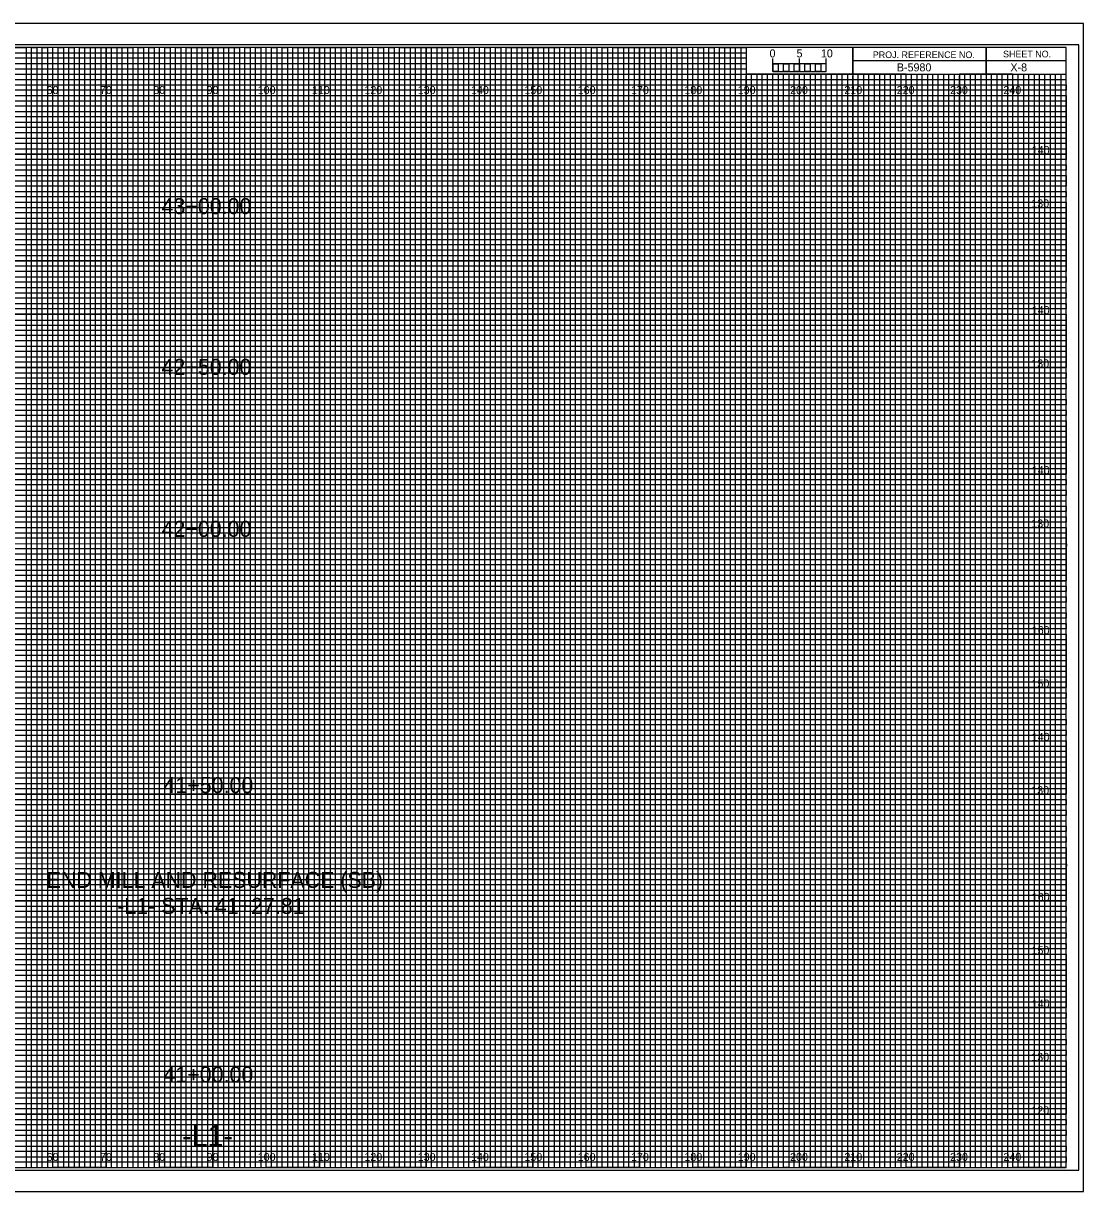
# Model space of a CAD drawing. Extents: x -13 to 323, y -5 to 3294.
# Drawn here: x 124.5 to 323.3, y 1535.5 to 1754.5 of the extents above; entities that cross this region are included whole.
import ezdxf

# ---------------------------------------------------------------- set-up
doc = ezdxf.new("R2010")
doc.units = 0
for name, color, linetype in [('Prop XS Alignment Label', 7, 'Continuous'), ('Prop XS Bar Scale Labels', 7, 'Continuous'), ('Prop XS Elevation Labels', 7, 'Continuous'), ('Prop XS Offset Labels', 7, 'Continuous'), ('Prop XS Project Number', 7, 'Continuous'), ('Prop XS Sheet Number', 7, 'Continuous'), ('Prop XS Station Labels', 7, 'Continuous'), ('Scratch_Level_0', 7, 'Continuous'), ('Sheet Cross Section CELL', 7, 'Continuous'), ('Sheet Cross Section Grid Major CELL', 7, 'Continuous'), ('Sheet Cross Section Grid Middle CELL', 7, 'Continuous'), ('Sheet Cross Section Grid Minor 1 CELL', 7, 'Continuous'), ('Sheet Cross Section Grid Minor 2 CELL', 7, 'Continuous'), ('Sheet Cross Section Scale CELL', 7, 'Continuous'), ('Sheet Cutting Line CELL', 7, 'Continuous'), ('Sheet DOT Grid CELL', 7, 'Continuous'), ('Sheet Plot Border Inside CELL', 7, 'Continuous'), ('Sheet Plot Border Outside CELL', 7, 'Continuous')]:
    doc.layers.add(name, color=color, linetype=linetype)

msp = doc.modelspace()

# ---------------------------------------------------------------- linework, layer by layer
at = {"layer": 'Scratch_Level_0'}
for points in [[(310, 1730), (10, 1730), (10, 1710), (310, 1710)], [(310, 1700), (10, 1700), (10, 1680), (310, 1680)], [(310, 1670), (10, 1670), (10, 1650), (310, 1650)], [(315, 1640), (10, 1640), (10, 1605), (315, 1605)], [(310, 1590), (10, 1590), (10, 1555), (310, 1555)]]:
    msp.add_lwpolyline(points, close=True, dxfattribs=at)
at = {"layer": 'Sheet Cross Section CELL'}
for p, q in [((305, 1750), (305, 1745)), ((305, 1745), (305, 1750)), ((280, 1747.5), (280, 1745)), ((320, 1747.49), (280, 1747.49)), ((280, 1745), (320, 1745))]:
    msp.add_line(p, q, dxfattribs=at)
for points in [[(320, 1750), (0, 1750), (0, 1540), (320, 1540)], [(280, 1750), (260, 1750), (260, 1745.03), (280, 1745.03)], [(320, 1750), (280, 1750), (280, 1745), (320, 1745)]]:
    msp.add_lwpolyline(points, close=True, dxfattribs=at)
at = {"layer": 'Sheet Cross Section Grid Major CELL'}
for p, q in [((130, 1750), (120, 1750)), ((130, 1540), (130, 1750)), ((150, 1750), (140, 1750)), ((140, 1750), (140, 1540)), ((150, 1540), (150, 1750)), ((170, 1750), (160, 1750)), ((160, 1750), (160, 1540)), ((170, 1540), (170, 1750)), ((190, 1750), (180, 1750)), ((180, 1750), (180, 1540)), ((190, 1540), (190, 1750)), ((210, 1750), (200, 1750)), ((200, 1750), (200, 1540)), ((210, 1540), (210, 1750)), ((230, 1750), (220, 1750)), ((220, 1750), (220, 1540)), ((230, 1540), (230, 1750)), ((250, 1750), (240, 1750)), ((240, 1750), (240, 1540)), ((250, 1540), (250, 1750)), ((260, 1750), (260, 1540)), ((270, 1540), (270, 1745)), ((290, 1745), (280, 1745)), ((280, 1745), (280, 1540)), ((290, 1540), (290, 1745)), ((310, 1745), (300, 1745)), ((300, 1745), (300, 1540)), ((310, 1540), (310, 1745)), ((140, 1540), (130, 1540)), ((160, 1540), (150, 1540)), ((180, 1540), (170, 1540)), ((200, 1540), (190, 1540)), ((220, 1540), (210, 1540)), ((240, 1540), (230, 1540)), ((260, 1540), (250, 1540)), ((280, 1540), (270, 1540)), ((300, 1540), (290, 1540)), ((320, 1540), (310, 1540)), ((320, 1540), (320, 1540))]:
    msp.add_line(p, q, dxfattribs=at)
for points in [[(0, 1740), (320, 1740), (320, 1730), (0, 1730)], [(0, 1720), (320, 1720), (320, 1710), (0, 1710)], [(0, 1700), (320, 1700), (320, 1690), (0, 1690)], [(0, 1680), (320, 1680), (320, 1670), (0, 1670)], [(0, 1660), (320, 1660), (320, 1650), (0, 1650)], [(0, 1640), (320, 1640), (320, 1630), (0, 1630)], [(0, 1620), (320, 1620), (320, 1610), (0, 1610)], [(0, 1600), (320, 1600), (320, 1590), (0, 1590)], [(0, 1580), (320, 1580), (320, 1570), (0, 1570)], [(0, 1560), (320, 1560), (320, 1550), (0, 1550)]]:
    msp.add_lwpolyline(points, dxfattribs=at)
at = {"layer": 'Sheet Cross Section Grid Middle CELL'}
for points in [[(115, 1750), (125, 1750), (125, 1540), (135, 1540), (135, 1750), (145, 1750), (145, 1540), (155, 1540), (155, 1750), (165, 1750), (165, 1540), (175, 1540), (175, 1750), (185, 1750), (185, 1540), (195, 1540), (195, 1750), (205, 1750), (205, 1540), (215, 1540), (215, 1750), (225, 1750), (225, 1540), (235, 1540), (235, 1750), (245, 1750), (245, 1540), (255, 1540), (255, 1750), (259.93, 1750), (260, 1750), (260, 1745), (264.99, 1745), (264.99, 1540), (275, 1540), (275, 1745), (285, 1745), (285, 1540), (295, 1540), (295, 1745), (305, 1745), (305, 1540), (315, 1540), (315, 1745)], [(0, 1745), (275, 1745)], [(0, 1725), (320, 1725), (320, 1735), (0, 1735)], [(0, 1705), (320, 1705), (320, 1715), (0, 1715)], [(0, 1685), (320, 1685), (320, 1695), (0, 1695)], [(0, 1665), (320, 1665), (320, 1675), (0, 1675)], [(0, 1645), (320, 1645), (320, 1655), (0, 1655)], [(0, 1625), (320, 1625), (320, 1635), (0, 1635)], [(0, 1605), (320, 1605), (320, 1615), (0, 1615)], [(0, 1585), (320, 1585), (320, 1595), (0, 1595)], [(0, 1565), (320, 1565), (320, 1575), (0, 1575)], [(0, 1545), (320, 1545), (320, 1555), (0, 1555)]]:
    msp.add_lwpolyline(points, dxfattribs=at)
at = {"layer": 'Sheet Cross Section Grid Minor 1 CELL'}
for p, q in [((0, 1749), (260, 1749)), ((260, 1747.98), (0, 1747.98)), ((260, 1749), (260, 1747.98)), ((0, 1747), (260, 1747)), ((260, 1745.89), (0, 1745.89)), ((260, 1747), (260, 1745.89)), ((0, 1744), (320, 1744))]:
    msp.add_line(p, q, dxfattribs=at)
for points in [[(0, 1743), (270, 1743), (320, 1743), (320, 1742), (0, 1742)], [(0, 1741), (320, 1741), (320, 1739), (0, 1739)], [(0, 1738), (320, 1738), (320, 1737), (0, 1736.98)], [(0, 1736), (320, 1736), (320, 1734), (0, 1734)], [(0, 1733), (320, 1733), (320, 1732), (0, 1732)], [(0, 1731), (320, 1731), (320, 1729), (0, 1729)], [(0, 1728), (320, 1728), (320, 1727), (0, 1727)], [(0, 1726), (320, 1726), (320, 1724), (0, 1724)], [(0, 1723), (320, 1723), (320, 1722), (0, 1722)], [(0, 1721), (320, 1721), (320, 1719), (0, 1719)], [(0, 1718), (320, 1718), (320, 1717), (0, 1717)], [(0, 1716), (320, 1716), (320, 1713.95), (320, 1713), (320, 1712), (0, 1712)], [(0, 1714), (320, 1714), (320, 1713), (0, 1713)], [(0, 1711), (320, 1711), (320, 1709), (0, 1709.03)], [(0, 1709.03), (320, 1709), (320, 1708), (0, 1708)], [(0, 1707), (320, 1707), (320, 1706), (0, 1706)], [(0, 1704), (320, 1704), (320, 1703), (0, 1703)], [(0, 1702), (320, 1702), (320, 1701), (0, 1701)], [(-0.07, 1698.89), (320, 1698.89), (320, 1697.88), (-0.07, 1697.88)], [(0, 1697), (320, 1697), (320, 1696), (0, 1696)], [(0, 1694), (320, 1694), (320, 1693), (0, 1693)], [(0, 1692), (320, 1692), (320, 1691), (0, 1691)], [(0, 1689), (320, 1689), (320, 1688), (0, 1688)], [(0, 1687), (320, 1687), (320, 1686), (0, 1686)], [(0, 1684), (320, 1684), (320, 1683), (0, 1683)], [(0, 1682), (320, 1682), (320, 1681), (0, 1681)], [(0, 1679), (320, 1679), (319.99, 1677.98), (0, 1678)], [(0, 1677), (320, 1677), (320, 1676), (0, 1676)], [(0, 1674), (320, 1674), (320, 1673), (0, 1673)], [(0, 1672), (320, 1672), (320, 1671), (0, 1671)], [(0, 1669), (320, 1669), (320, 1668), (0, 1668)], [(0, 1667), (320, 1667), (320, 1666), (0, 1666)], [(0, 1664), (320, 1664), (320, 1663), (0, 1663)], [(0, 1662), (320, 1662), (320, 1661), (0, 1661)], [(0, 1659), (320, 1659), (320, 1658), (0, 1658)], [(0, 1656.99), (320.07, 1656.91), (320, 1656), (0, 1656)], [(0, 1654), (320, 1654), (320, 1653), (0, 1653)], [(0, 1652), (320, 1652), (320, 1651), (0, 1651)], [(0, 1649), (320, 1649), (320, 1648), (0, 1648)], [(0, 1647), (320, 1647), (320, 1646), (0, 1646)], [(0, 1644), (320, 1644), (320, 1643), (0, 1643)], [(0, 1642), (320, 1642), (320, 1641), (0, 1641)], [(0, 1639), (320, 1639), (320, 1638), (0, 1638)], [(0, 1637), (320, 1637), (320, 1636), (0, 1636)], [(0, 1634), (320, 1634), (320, 1633), (0, 1633)], [(0, 1632), (320, 1632), (320, 1631), (0, 1631)], [(0, 1629), (320, 1629), (320, 1628), (0, 1628)], [(0, 1627), (320, 1627), (320, 1626), (0, 1626)], [(0, 1624), (320, 1624), (320, 1623), (0, 1623)], [(0, 1622), (320, 1622), (320, 1621), (0, 1621)], [(0, 1619), (320, 1619), (319.99, 1617.98), (0, 1618)], [(0, 1617), (320, 1617), (320, 1616), (0, 1616)], [(0, 1614), (320, 1614), (320, 1613), (0, 1613)], [(0, 1612), (320, 1612), (320, 1611), (0, 1611)], [(0, 1609), (320, 1609), (320, 1608), (0, 1608)], [(0, 1607), (320, 1607), (320, 1606), (0, 1606)], [(0, 1604), (320, 1604), (320, 1603), (0, 1603)], [(0, 1602), (320, 1602), (320, 1601), (0, 1601)], [(0, 1599), (320, 1599), (320, 1598), (0, 1598)], [(0, 1596.99), (320.07, 1596.91), (320, 1596), (0, 1596)], [(0, 1594), (320, 1594), (320, 1593), (0, 1593)], [(0, 1592), (320, 1592), (320, 1591), (0, 1591)], [(0, 1589), (320, 1589), (320, 1588), (0, 1588)], [(0, 1587), (320, 1587), (320, 1586), (0, 1586)], [(0, 1584), (320, 1584), (320, 1583), (0, 1583)], [(0, 1582), (320, 1582), (320, 1581), (0, 1581)], [(0, 1579), (320, 1579), (320, 1578), (0, 1578)], [(0, 1577), (320, 1577), (320, 1576), (0, 1576)], [(0, 1574), (320, 1574), (320, 1573), (0, 1573)], [(0, 1572), (320, 1572), (320, 1571), (0, 1571)], [(0, 1569), (320, 1569), (320, 1568), (0, 1568)], [(0, 1567), (320, 1567), (320, 1566), (0, 1566)], [(0, 1564), (320, 1564), (320, 1563), (0, 1563)], [(0, 1562), (320, 1562), (320, 1561), (0, 1561)], [(0, 1559), (320, 1559), (320, 1558), (0, 1558)], [(0, 1557), (320, 1557), (320, 1556), (0, 1556)], [(0, 1554), (320, 1554), (320, 1553), (0, 1553)], [(0, 1552), (320, 1552), (320, 1551), (0, 1551)], [(0, 1549), (320, 1549), (320, 1548), (0, 1548)], [(0, 1547), (320, 1547), (320, 1546), (0, 1546)], [(0, 1544), (320, 1544), (320, 1543), (0, 1543)], [(0, 1542), (320, 1542), (320, 1541), (0, 1541)]]:
    msp.add_lwpolyline(points, dxfattribs=at)
at = {"layer": 'Sheet Cross Section Grid Minor 2 CELL'}
for p, q in [((267, 1745), (266.01, 1745)), ((266.01, 1745), (266.01, 1540)), ((267, 1540), (267, 1745)), ((269, 1745), (268, 1745)), ((268, 1745), (268, 1540)), ((269, 1540), (269, 1745)), ((266.01, 1540), (265, 1540)), ((268, 1540), (267, 1540))]:
    msp.add_line(p, q, dxfattribs=at)
for points in [[(125, 1540), (126, 1540), (126, 1750), (127, 1750), (127, 1540)], [(127, 1540), (128, 1540), (128, 1750), (129, 1750), (129, 1540)], [(130, 1540), (131, 1540), (131, 1750), (132, 1750), (132, 1540)], [(132, 1540), (133, 1540), (133, 1750), (134, 1750), (134, 1540)], [(135, 1540), (136, 1540), (136, 1750), (137, 1750), (137, 1540)], [(137, 1540), (138, 1540), (138, 1750), (139, 1750), (139, 1540)], [(140, 1540), (141, 1540), (141, 1750), (142, 1750), (142, 1540)], [(142, 1540), (143, 1540), (143, 1750), (144, 1750), (144, 1540)], [(145, 1540), (146, 1540), (146, 1750), (147, 1750), (147, 1540)], [(147, 1540), (148, 1540), (148, 1750), (149, 1750), (149, 1540)], [(150, 1540), (151, 1540), (151, 1750), (152, 1750), (152, 1540)], [(152, 1540), (153, 1540), (153, 1750), (154, 1750), (154, 1540)], [(155, 1540), (156, 1540), (156, 1750), (157, 1750), (157, 1540)], [(157, 1540), (158, 1540), (158, 1750), (159, 1750), (159, 1540)], [(160, 1540), (161, 1540), (161, 1750), (162, 1750), (162, 1540)], [(162, 1540), (163, 1540), (163, 1750), (164, 1750), (164, 1540)], [(165, 1540), (166, 1540), (166, 1750), (167, 1750), (167, 1540)], [(167, 1540), (168, 1540), (168, 1750), (169, 1750), (169, 1540)], [(170, 1540), (171, 1540), (171, 1750), (172, 1750), (172, 1540)], [(172, 1540), (173, 1540), (173, 1750), (174, 1750), (174, 1540)], [(175, 1540), (176, 1540), (176, 1750), (177, 1750), (177, 1540)], [(177, 1540), (178, 1540), (178, 1750), (179, 1750), (179, 1540)], [(180, 1540), (181, 1540), (181, 1750), (182, 1750), (182, 1540)], [(182, 1540), (183, 1540), (183, 1750), (184, 1750), (184, 1540)], [(185, 1540), (186, 1540), (186, 1750), (187, 1750), (187, 1540)], [(187, 1540), (188, 1540), (188, 1750), (189, 1750), (189, 1540)], [(190, 1540), (191, 1540), (191, 1750), (192, 1750), (192, 1540)], [(192, 1540), (193, 1540), (193, 1750), (194, 1750), (194, 1540)], [(195, 1540), (196, 1540), (196, 1750), (197, 1750), (197, 1540)], [(197, 1540), (198, 1540), (198, 1750), (199, 1750), (199, 1540)], [(200, 1540), (201, 1540), (201, 1750), (202, 1750), (202, 1540)], [(202, 1540), (203, 1540), (203, 1750), (204, 1750), (204, 1540)], [(205, 1540), (206, 1540), (206, 1750), (207, 1750), (207, 1540)], [(207, 1540), (208, 1540), (208, 1750), (209, 1750), (209, 1540)], [(210, 1540), (211, 1540), (211, 1750), (212, 1750), (212, 1540)], [(212, 1540), (213, 1540), (213, 1750), (214, 1750), (214, 1540)], [(215, 1540), (216, 1540), (216, 1750), (217, 1750), (217, 1540)], [(217, 1540), (218, 1540), (218, 1750), (219, 1750), (219, 1540)], [(220, 1540), (221, 1540), (221, 1750), (222, 1750), (222, 1540)], [(222, 1540), (223, 1540), (223, 1750), (224, 1750), (224, 1540)], [(225, 1540), (226, 1540), (226, 1750), (227, 1750), (227, 1540)], [(227, 1540), (228, 1540), (228, 1750), (229, 1750), (229, 1540)], [(230, 1540), (231, 1540), (231, 1750), (232, 1750), (232, 1540)], [(232, 1540), (233, 1540), (233, 1750), (234, 1750), (234, 1540)], [(235, 1540), (236, 1540), (236, 1750), (237, 1750), (237, 1540)], [(237, 1540), (238, 1540), (238, 1750), (239, 1750), (239, 1540)], [(240, 1540), (241, 1540), (241, 1750), (242, 1750), (242, 1540)], [(242, 1540), (243, 1540), (243, 1750), (244, 1750), (244, 1540)], [(245, 1540), (246, 1540), (246, 1750), (247, 1750), (247, 1540)], [(247, 1540), (248, 1540), (248, 1750), (249, 1750), (249, 1540)], [(250, 1540), (251, 1540), (251, 1750), (252, 1750), (252, 1540)], [(252, 1540), (253, 1540), (253, 1750), (254, 1750), (254, 1540)], [(255, 1540), (256, 1540), (256, 1750), (257, 1750), (257, 1540)], [(257, 1540), (258, 1540), (258, 1750), (259, 1750), (259, 1540)], [(260, 1540), (261, 1540), (261, 1745), (262.02, 1745), (262.02, 1540)], [(262, 1540), (263, 1540), (263, 1745), (263.99, 1745), (263.99, 1540)], [(270, 1540), (270.98, 1540), (270.98, 1745), (272, 1745), (272, 1540)], [(272, 1540), (273, 1540), (273, 1745), (274.05, 1745), (274.05, 1540)], [(275, 1540), (276, 1540), (276, 1745), (277, 1745), (277, 1540)], [(277, 1540), (278, 1540), (278, 1745), (279, 1745), (279, 1540)], [(280, 1540), (281, 1540), (281, 1745), (282, 1745), (282, 1540)], [(282, 1540), (283, 1540), (283, 1745), (284, 1745), (284, 1540)], [(285, 1540), (286, 1540), (286, 1745), (287, 1745), (287, 1540)], [(287, 1540), (288, 1540), (288, 1745), (289, 1745), (289, 1540)], [(290, 1540), (291, 1540), (291, 1745), (292, 1745), (292, 1540)], [(292, 1540), (293, 1540), (293, 1745), (294, 1745), (294, 1540)], [(295, 1540), (296, 1540), (296, 1745), (297, 1745), (297, 1540)], [(297, 1540), (298, 1540), (298, 1745), (299, 1745), (299, 1540)], [(300, 1540), (301, 1540), (301, 1745), (302, 1745), (302, 1540)], [(302, 1540), (303, 1540), (303, 1745), (304, 1745), (304, 1540)], [(305, 1540), (306, 1540), (306, 1745), (307, 1745), (307, 1540)], [(307, 1540), (308, 1540), (308, 1745), (309, 1745), (309, 1540)], [(310, 1540), (311, 1540), (311, 1745), (312, 1745), (312, 1540)], [(312, 1540), (313, 1540), (313, 1745), (314, 1745), (314, 1540)], [(315, 1540), (316, 1540), (316, 1745), (317, 1745), (317, 1540)], [(317, 1540), (318, 1540), (318, 1745), (319, 1745), (319, 1540)]]:
    msp.add_lwpolyline(points, dxfattribs=at)
at = {"layer": 'Sheet Cross Section Scale CELL'}
for p, q in [((265, 1745.49), (265, 1747.9)), ((265, 1746.9), (265, 1747.9)), ((270, 1745.49), (270, 1747.9)), ((275, 1745.49), (275, 1747.9)), ((275, 1746.9), (275, 1747.9))]:
    msp.add_line(p, q, dxfattribs=at)
for points in [[(275, 1746.9), (265, 1746.9), (265, 1745.49), (275, 1745.49)], [(265, 1746.9), (266, 1746.9), (266, 1745.49), (265, 1745.49)], [(267, 1746.9), (268, 1746.9), (268, 1745.49), (267, 1745.49)], [(269, 1746.9), (270, 1746.9), (270, 1745.49), (269, 1745.49)], [(271, 1746.9), (272, 1746.9), (272, 1745.49), (271, 1745.49)], [(273, 1746.9), (274, 1746.9), (274, 1745.49), (273, 1745.49)]]:
    msp.add_lwpolyline(points, close=True, dxfattribs=at)
at = {"layer": 'Sheet Cutting Line CELL'}
for p, q in [((323.3, 1754.5), (-13.4, 1754.5)), ((-13.4, 1535.5), (323.3, 1535.5))]:
    msp.add_line(p, q, dxfattribs=at)
at = {"layer": 'Sheet DOT Grid CELL'}
for p, q in [((130, 1540), (130, 1750)), ((140, 1540), (140, 1750)), ((150, 1540), (150, 1750)), ((160, 1540), (160, 1750)), ((170, 1540), (170, 1750)), ((180, 1540), (180, 1750)), ((190, 1540), (190, 1750)), ((200, 1540), (200, 1750)), ((210, 1540), (210, 1750)), ((220, 1540), (220, 1750)), ((230, 1540), (230, 1750)), ((240, 1540), (240, 1750)), ((250, 1540), (250, 1750)), ((260, 1540), (260, 1744.69)), ((270, 1540), (270, 1744.69)), ((280, 1540), (280, 1744.69)), ((290, 1540), (290, 1744.69)), ((300, 1540), (300, 1744.69)), ((310, 1540), (310, 1744.69)), ((0, 1740), (320, 1740)), ((0, 1730), (320, 1730)), ((0, 1720), (320, 1720)), ((0, 1710), (320, 1710)), ((0, 1700), (320, 1700)), ((0, 1690), (320, 1690)), ((0, 1680), (320, 1680)), ((0, 1670), (320, 1670)), ((0, 1660), (320, 1660)), ((0, 1650), (320, 1650)), ((0, 1640), (320, 1640)), ((0, 1630), (320, 1630)), ((0, 1620), (320, 1620)), ((0, 1610), (320, 1610)), ((0, 1600), (320, 1600)), ((0, 1590), (320, 1590)), ((0, 1580), (320, 1580)), ((0, 1570), (320, 1570)), ((0, 1560), (320, 1560)), ((0, 1550), (320, 1550))]:
    msp.add_line(p, q, dxfattribs=at)
at = {"layer": 'Sheet Plot Border Inside CELL'}
msp.add_lwpolyline([(-10.8, 1539.5), (322.4, 1539.5), (322.4, 1750.5), (-10.8, 1750.5)], close=True, dxfattribs=at)
at = {"layer": 'Sheet Plot Border Outside CELL'}
msp.add_lwpolyline([(-13.4, 1535.5), (323.3, 1535.5), (323.3, 1754.5), (-13.4, 1754.5)], close=True, dxfattribs=at)

# ---------------------------------------------------------------- texts
at = {"layer": 'Prop XS Alignment Label'}
msp.add_text('-L1-', height=4, dxfattribs=at).set_placement((154.28, 1544))
at = {"layer": 'Prop XS Bar Scale Labels'}
for s, p in [('5', (269.47, 1748.12)), ('10', (274.04, 1748.12))]:
    msp.add_text(s, height=1.5, dxfattribs=at).set_placement(p)
at = {"layer": 'Prop XS Elevation Labels'}
for s, p in [('140', (313.57, 1730)), ('130', (313.49, 1720)), ('140', (313.57, 1700)), ('130', (313.49, 1690)), ('140', (313.57, 1670)), ('130', (313.49, 1660)), ('160', (313.57, 1640)), ('150', (313.52, 1630)), ('140', (313.57, 1620)), ('130', (313.49, 1610)), ('160', (313.57, 1590)), ('150', (313.52, 1580)), ('140', (313.57, 1570)), ('130', (313.49, 1560)), ('120', (313.5, 1550))]:
    msp.add_text(s, height=1.5, dxfattribs=at).set_placement(p)
at = {"layer": 'Prop XS Offset Labels'}
for s, p in [('60', (128.86, 1741.25)), ('70', (138.86, 1741.25)), ('80', (148.86, 1741.25)), ('90', (158.86, 1741.25)), ('100', (168.44, 1741.25)), ('110', (178.62, 1741.25)), ('120', (188.44, 1741.25)), ('130', (198.44, 1741.25)), ('140', (208.44, 1741.25)), ('150', (218.44, 1741.25)), ('160', (228.44, 1741.25)), ('170', (238.44, 1741.25)), ('180', (248.44, 1741.25)), ('190', (258.44, 1741.25)), ('200', (268.26, 1741.25)), ('210', (278.44, 1741.25)), ('220', (288.26, 1741.25)), ('230', (298.26, 1741.25)), ('240', (308.26, 1741.25)), ('60', (128.86, 1541.25)), ('70', (138.86, 1541.25)), ('80', (148.86, 1541.25)), ('90', (158.86, 1541.25)), ('100', (168.44, 1541.25)), ('110', (178.62, 1541.25)), ('120', (188.44, 1541.25)), ('130', (198.44, 1541.25)), ('140', (208.44, 1541.25)), ('150', (218.44, 1541.25)), ('160', (228.44, 1541.25)), ('170', (238.44, 1541.25)), ('180', (248.44, 1541.25)), ('190', (258.44, 1541.25)), ('200', (268.26, 1541.25)), ('210', (278.44, 1541.25)), ('220', (288.26, 1541.25)), ('230', (298.26, 1541.25)), ('240', (308.26, 1541.25))]:
    msp.add_text(s, height=1.5, dxfattribs=at).set_placement(p)
at = {"layer": 'Prop XS Project Number'}
msp.add_text('B-5980', height=1.5, dxfattribs=at).set_placement((288.28, 1745.5))
at = {"layer": 'Prop XS Sheet Number'}
msp.add_text('X-8', height=1.5, dxfattribs=at).set_placement((309.57, 1745.5))
at = {"layer": 'Prop XS Station Labels'}
for s, p in [('43+00.00', (150.41, 1718.75)), ('42+50.00', (150.41, 1688.61)), ('42+00.00', (150.41, 1658.24)), ('41+50.00', (150.77, 1610.21)), ('END MILL AND RESURFACE (SB)', (128.87, 1592.44)), ('-L1- STA. 41+27.81', (142.11, 1587.56)), ('41+00.00', (150.77, 1555.97))]:
    msp.add_text(s, height=3, dxfattribs=at).set_placement(p)
at = {"layer": 'Sheet Cross Section CELL'}
for s, p in [('PROJ. REFERENCE NO.', (283.77, 1747.99)), ('SHEET NO.', (308.19, 1748.12))]:
    msp.add_text(s, height=1.25, dxfattribs=at).set_placement(p)
at = {"layer": 'Sheet Cross Section Scale CELL'}
msp.add_text('0', height=1.5, dxfattribs=at).set_placement((264.41, 1748.12))

doc.saveas('drawing.dxf')
